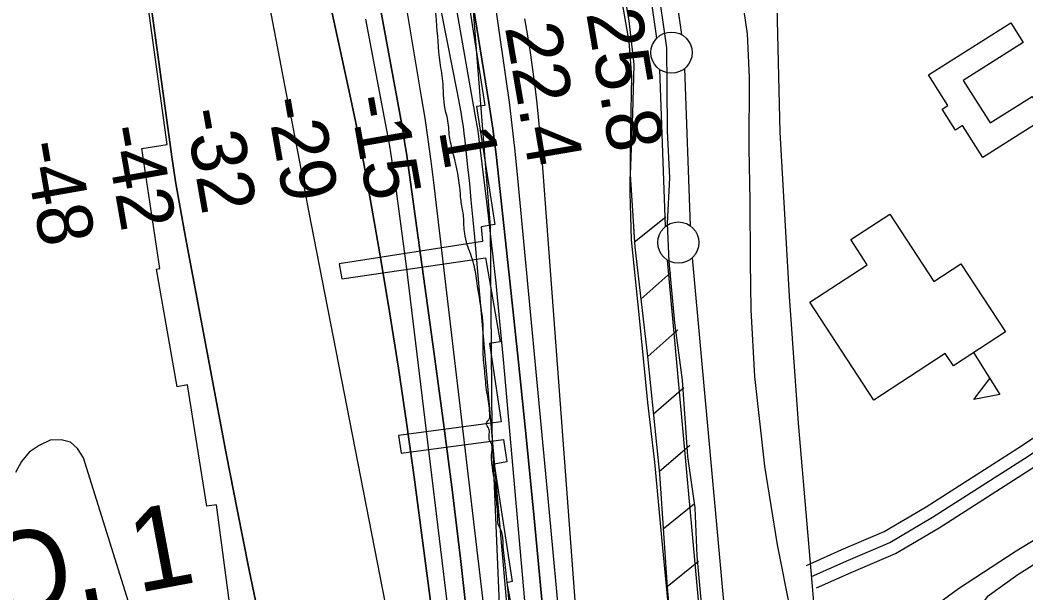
# Model space of a CAD drawing. Extents: x 3419139 to 3457078, y 540382 to 565875.
# Drawn here: x 3439941 to 3441162, y 549163 to 549858 of the extents above; entities that cross this region are included whole.
import ezdxf

# ---------------------------------------------------------------- set-up
doc = ezdxf.new("R2010")
doc.units = 0
for name, color, linetype in [('V-BLDG-OTLN', 7, 'Continuous'), ('V-CHAN-NAID', 7, 'Continuous'), ('V-FLOD-BASE', 7, 'Continuous'), ('V-LEVE-TOET', 7, 'Continuous'), ('V-RIVR-EDGE', 7, 'Continuous'), ('V-RIVR-RANG', 7, 'Continuous'), ('V-ROAD-CNTR', 7, 'Continuous'), ('V-RRAP-FSHR', 7, 'Continuous'), ('V-RRAP-RVMT', 7, 'Continuous'), ('V-SITE-VEGE', 7, 'Continuous'), ('V-SURV-LINE', 7, 'Continuous'), ('V-TOPO-DPTH', 7, 'Continuous'), ('V-TOPO-MAJR', 7, 'Continuous'), ('V-TOPO-MINR', 7, 'Continuous'), ('V-TOPO-WATR', 7, 'Continuous')]:
    doc.layers.add(name, color=color, linetype=linetype)

msp = doc.modelspace()

# ---------------------------------------------------------------- linework, layer by layer
at = {"layer": 'V-BLDG-OTLN'}
msp.add_line((3441098.3, 549454.1), (3441130.3, 549403.3), dxfattribs=at)
for points in [[(3441185.7, 549738.9), (3441109.7, 549690.7), (3441085.1, 549729.7), (3441076.4, 549724.2), (3441060.2, 549749.6), (3441067.2, 549754), (3441043.7, 549791.1), (3441143.4, 549854.3), (3441158.5, 549830.4), (3441085.9, 549784.3), (3441118.6, 549732.7), (3441169.3, 549764.9)], [(3440977.4, 549396.5), (3440899.6, 549515.2), (3440969.3, 549560.8), (3440949.4, 549591.2), (3440996.6, 549622), (3441050.1, 549540.4), (3441083, 549562), (3441137.1, 549479.5), (3441073.9, 549438), (3441063.9, 549453.2)], [(3441130.3, 549403.3), (3441098.8, 549397.1), (3441118, 549422.9)]]:
    msp.add_lwpolyline(points, close=True, dxfattribs=at)
at = {"layer": 'V-FLOD-BASE'}
msp.add_lwpolyline([(3440714, 549906), (3440725.6, 549823.7), (3440726.1, 549777.7), (3440726.5, 549723), (3440729.2, 549666.2), (3440726.5, 549611.2), (3440728.4, 549564.6), (3440735.5, 549490.2), (3440744.9, 549420.6), (3440751.1, 549327.9), (3440760, 549265.6), (3440762.4, 549207.5), (3440767.6, 549149.9), (3440775.3, 549076.3), (3440784.3, 548990.4), (3440791.4, 548896.6), (3440799.1, 548820.8), (3440806.5, 548751.4), (3440810.9, 548694.7), (3440820.2, 548621.4), (3440826.8, 548551.8), (3440832.8, 548485.5), (3440841.1, 548407.2)], dxfattribs=at)
at = {"layer": 'V-LEVE-TOET'}
for points in [[(3440789.6, 548428.9), (3440784.4, 548485.5), (3440775.6, 548556.9), (3440769.9, 548621.4), (3440766.4, 548676.6), (3440760.7, 548752.2), (3440753, 548819.5), (3440745.9, 548897.4), (3440740.2, 548970.5), (3440733.1, 549061.3), (3440727.7, 549150.1), (3440720, 549229.7), (3440711.6, 549321.3), (3440703.1, 549393.6), (3440692.7, 549500.3), (3440683.3, 549590.8), (3440681.5, 549648.3), (3440682.5, 549727.3), (3440683.8, 549788.6), (3440680.5, 549831.5), (3440669.5, 549894.3)], [(3440819.4, 549868.4), (3440823.5, 549841), (3440825.9, 549787.7), (3440825.5, 549702), (3440827, 549638.4), (3440827.1, 549564.5), (3440828.1, 549505.9), (3440832.4, 549425), (3440844.7, 549316.5), (3440859.9, 549220.9), (3440875.7, 549141.6), (3440885.5, 549042.4), (3440892.6, 548950.3), (3440904.7, 548845.2), (3440911.9, 548790.8), (3440921.3, 548737.6), (3440930.4, 548685.2), (3440939.2, 548620.7), (3440947.4, 548543.1), (3440959.2, 548434.1)]]:
    msp.add_lwpolyline(points, dxfattribs=at)
at = {"layer": 'V-RIVR-EDGE'}
msp.add_spline([(3440606.5, 548542), (3440606.2, 548567.3), (3440602.8, 548588.8), (3440599.6, 548602.9), (3440598.6, 548615.3), (3440596.9, 548630.4), (3440593.4, 548648.4), (3440585, 548681.9), (3440580.8, 548696.7), (3440577.3, 548705.2), (3440573.8, 548711.9), (3440574.2, 548719.3), (3440574.9, 548725.6), (3440572.5, 548739), (3440569.7, 548758.4), (3440569.8, 548774.6), (3440568.4, 548805.6), (3440568.5, 548828.2), (3440566.4, 548832.8), (3440561.1, 548843), (3440560.8, 548848.3), (3440560.8, 548854.6), (3440560.5, 548859.6), (3440561.9, 548864.1), (3440565.4, 548871.5), (3440566.5, 548880.3), (3440566.2, 548891.3), (3440563.4, 548894.8), (3440561.3, 548896.9), (3440560.6, 548898.3), (3440558.8, 548902.2), (3440558.5, 548910.7), (3440559.2, 548920.9), (3440561.7, 548937.1), (3440562.4, 548945.5), (3440562.4, 548952.6), (3440561.8, 548959.3), (3440559.7, 548969.1), (3440557.6, 548979), (3440555.5, 548989.9), (3440553, 548999.8), (3440549.9, 549013.6), (3440549.9, 549021.7), (3440550, 549031.9), (3440548.9, 549037.9), (3440547.2, 549043.2), (3440545.1, 549050.9), (3440542.7, 549081.6), (3440541.7, 549102.7), (3440541.4, 549115.8), (3440539.6, 549121.4), (3440538.2, 549126.4), (3440533.7, 549164.8), (3440530.3, 549193.7), (3440527.5, 549221.9), (3440525.8, 549236), (3440521.2, 549247.6), (3440520.9, 549255.4), (3440519.2, 549278.3), (3440518.5, 549290.3), (3440515.4, 549308.2), (3440514.4, 549315.3), (3440513.7, 549332.9), (3440512.7, 549345.6), (3440510.6, 549348.8), (3440510.6, 549351.9), (3440510.6, 549355.5), (3440510.9, 549359), (3440510.2, 549361.5), (3440507.1, 549368.5), (3440511, 549374.1), (3440511.3, 549378.4), (3440511, 549384), (3440507.9, 549405.9), (3440505.1, 549431.6), (3440503.1, 549458.4), (3440503.2, 549487.3), (3440501.4, 549504.5), (3440495.9, 549538.4), (3440492.1, 549561), (3440488.2, 549573.3), (3440484, 549584.9), (3440480.9, 549598.7), (3440479.9, 549608.6), (3440479.5, 549619.1), (3440476.7, 549636.4), (3440475, 549654.4), (3440466, 549699.9), (3440462.2, 549718.9), (3440459.4, 549740.7), (3440458, 549745.3), (3440454.6, 549780.2), (3440451.1, 549806), (3440446.6, 549857.1), (3440441.5, 549900.4), (3440437, 549938.1), (3440435.9, 549948.7), (3440428.7, 549999.8), (3440424.8, 550021.7), (3440423.5, 550042.1), (3440422.2, 550073.5), (3440419.1, 550101), (3440415.2, 550128.5), (3440409, 550157.7), (3440408, 550174.3), (3440409.4, 550193.7), (3440408.7, 550210.2), (3440405.6, 550227.2), (3440403.9, 550234.9), (3440395.8, 550244.4), (3440387, 550251.5), (3440378.6, 550256.1), (3440372.9, 550264.2), (3440367, 550279), (3440361.8, 550306.2), (3440354.8, 550346), (3440348.9, 550377.8), (3440347.9, 550389.7), (3440349, 550403.1), (3440352.5, 550418.3), (3440352.5, 550423.6), (3440351.1, 550427.4), (3440341.7, 550443), (3440332.5, 550450), (3440330.1, 550453.6), (3440325.2, 550467), (3440324.2, 550488.8), (3440325.3, 550503.3), (3440325.7, 550521.2), (3440325, 550535.3), (3440320.4, 550554.4), (3440313.8, 550578.3), (3440311.7, 550592.1), (3440311.8, 550613.2), (3440308, 550646.7), (3440307.7, 550672.1), (3440307.7, 550684.4), (3440304.2, 550695.4), (3440300.4, 550703.8), (3440296.5, 550714.4), (3440295.5, 550723.9), (3440295.9, 550738.4), (3440295.9, 550747.5), (3440291.4, 550757.4), (3440287.5, 550775.4), (3440284.4, 550791.6), (3440282.7, 550806.4), (3440279.9, 550812.8), (3440279.9, 550816.6), (3440276.7, 550830.7), (3440272.2, 550850.1), (3440262.8, 550882.2), (3440257.2, 550910.8), (3440255.5, 550936.2), (3440255.5, 550947.8), (3440257.7, 550957.3), (3440260.5, 550966.1), (3440264.4, 550979.8), (3440264.1, 550991.1), (3440262, 551009.8), (3440258.5, 551023.5), (3440256.4, 551033.4), (3440256.5, 551038.7), (3440260.7, 551046.4), (3440260.7, 551055.2), (3440257.2, 551067.9), (3440250.9, 551083.8), (3440245.7, 551098.3), (3440234.1, 551119.4), (3440230.2, 551127.6), (3440228.1, 551132.5), (3440221.5, 551140.3), (3440218.3, 551147), (3440212.4, 551159.7), (3440202.6, 551196.3), (3440198, 551213.3), (3440198.1, 551219.3), (3440197.4, 551227.4), (3440196.7, 551237.6), (3440192.8, 551245.7), (3440189.7, 551257), (3440187.3, 551269), (3440183.1, 551289.4), (3440182.4, 551301.7), (3440179.6, 551313.7), (3440175.4, 551332.4), (3440174.1, 551344.8), (3440172.7, 551357.1), (3440172.3, 551367.7), (3440172, 551383.2), (3440172.4, 551398.3), (3440171.1, 551413.5), (3440170, 551424.1), (3440167.9, 551425.8), (3440162.6, 551434.3), (3440159.9, 551454.4), (3440156, 551470.6), (3440152.9, 551490.3), (3440152.9, 551495.3), (3440155.8, 551496.3), (3440155.4, 551498.8), (3440149.8, 551521.4), (3440146.3, 551534.8), (3440142.2, 551559.1)], degree=3, dxfattribs=at)
at = {"layer": 'V-ROAD-CNTR'}
for points in [[(3440806.5, 550262.5), (3440829.5, 550127), (3440847.5, 549995.6), (3440859.7, 549874.2), (3440863.2, 549721.4), (3440874.4, 549522.6), (3440885.6, 549368.5), (3440909.1, 549095.1), (3440935, 548822.8), (3440956.6, 548577.1), (3440983.9, 548304.6)], [(3440895.5, 549196), (3440937.8, 549215), (3440990, 549237.1), (3441040.8, 549267.2), (3441152, 549338.2), (3441296.5, 549433.6), (3441402.1, 549505.5)], [(3440901.6, 549182.3), (3440943.8, 549201.2), (3440996.8, 549223.7), (3441048.7, 549254.5), (3441160.1, 549325.6), (3441304.9, 549421.2), (3441410.6, 549493.1)], [(3440907.7, 549168.6), (3440949.8, 549187.5), (3441003.6, 549210.3), (3441056.5, 549241.7), (3441168.3, 549313), (3441313.2, 549408.7), (3441419, 549480.7)]]:
    msp.add_lwpolyline(points, dxfattribs=at)
at = {"layer": 'V-RRAP-FSHR'}
for p, q in [((3440686.8, 549588.4), (3440724.9, 549618.8)), ((3440694.6, 549518.9), (3440731.1, 549551.4)), ((3440702.9, 549449.3), (3440739.3, 549481.9)), ((3440709.9, 549379.7), (3440746.9, 549411.6)), ((3440716.9, 549310), (3440753.9, 549341.9)), ((3440721.7, 549240.2), (3440759.7, 549270.9)), ((3440726.5, 549170.4), (3440764.5, 549201))]:
    msp.add_line(p, q, dxfattribs=at)
for points in [[(3439977.8, 552420.6), (3440106.4, 551780.9), (3440172.3, 551404.3), (3440232, 551110), (3440392.8, 550607.1), (3440489.2, 549894.4), (3440511.6, 549607.3), (3440513.8, 549359.3), (3440532, 548929.5), (3440619.8, 548305.6), (3440691.1, 548058.6), (3440757.3, 547660.9), (3440767.5, 547537.4), (3440783.9, 547406), (3441072.2, 545849.7)], [(3440614, 550282.7), (3440634.7, 550166.5), (3440663.2, 549954.4), (3440680, 549856.7), (3440686, 549803.7), (3440684.6, 549744.2), (3440681.7, 549670.3), (3440687.2, 549581.9), (3440702.8, 549449.4), (3440717.2, 549307.2), (3440726.6, 549169.2), (3440746, 548958.9), (3440764.7, 548717.6), (3440769.3, 548594), (3440791.4, 548435.6)], [(3440685.6, 549606.4), (3440687.2, 549581.9), (3440702.8, 549449.4), (3440717.2, 549307.2), (3440726.6, 549169.2), (3440729.1, 549142.2)]]:
    msp.add_lwpolyline(points, dxfattribs=at)
at = {"layer": 'V-RRAP-RVMT'}
for points in [[(3440106.8, 549555.5), (3440110.8, 549556.1), (3440089, 549701.8), (3440119.9, 549706.7), (3440046.8, 550237.4), (3440021.9, 550234.5), (3439978.8, 550522.5), (3439962.8, 550519.8), (3439939.3, 550673.8), (3439942.1, 550674.4), (3439921.8, 550804.9), (3439910.5, 550803.2), (3439869, 551057.2), (3439876.9, 551058.9), (3439860.3, 551163), (3439850.8, 551161.3), (3439834.7, 551249.1)], [(3440484.7, 549885.6), (3440505.2, 549754.1), (3440495.1, 549752.7), (3440517.6, 549609.5), (3440500.7, 549606.9), (3440502.5, 549589.1), (3440328.6, 549562), (3440331.8, 549543.5), (3440506, 549569.2), (3440523.7, 549467.1)], [(3440292.6, 548413.6), (3440272.2, 548548.6), (3440262.2, 548546.9), (3440219.9, 548847.1), (3440226.4, 548848.2), (3440205.9, 548992.5), (3440209.7, 548993.1), (3440190.6, 549137.2), (3440197, 549138.4), (3440179.7, 549269.5), (3440168, 549267.7), (3440144.6, 549415), (3440132.1, 549412.7), (3440106.8, 549555.5)], [(3440523.7, 549467.1), (3440510.8, 549465), (3440524.9, 549370.1), (3440400.6, 549353.5), (3440403.9, 549332.3), (3440527.9, 549348.7), (3440531.9, 549321.7), (3440516.8, 549318.9), (3440538.5, 549176.6), (3440531.9, 549174.9), (3440536.6, 549150.8)]]:
    msp.add_lwpolyline(points, dxfattribs=at)
at = {"layer": 'V-SITE-VEGE'}
msp.add_lwpolyline([(3441195.7, 549212.1), (3441151.9, 549184.5), (3441115, 549157.7), (3441108.1, 549148.4), (3441103.8, 549140.2), (3441093.6, 549134.8), (3441087.5, 549135.5), (3441074, 549135.5), (3441054.9, 549124.1), (3441030.7, 549107.5), (3441015, 549100), (3441007.5, 549100), (3441002.4, 549104.3), (3441001.8, 549110.6), (3441026.9, 549129), (3441080.1, 549168.1), (3441150.2, 549213.8), (3441251.7, 549275.4)], dxfattribs=at)
at = {"layer": 'V-SURV-LINE'}
for points in [[(3440714.1, 549835.8), (3440635.6, 550387)], [(3440665.3, 550391.2), (3440743.8, 549840)], [(3440724.4, 549607), (3440717.5, 549797.6)], [(3440747.5, 549798.7), (3440754.4, 549608.1)], [(3440823.7, 548506.7), (3440727, 549566.3)], [(3440756.9, 549569.1), (3440853.6, 548509.4)]]:
    msp.add_lwpolyline(points, dxfattribs=at)
for centre in [(3440731.8, 549818.1), (3440740.1, 549587.6)]:
    msp.add_circle(centre, 25, dxfattribs=at)
at = {"layer": 'V-TOPO-DPTH'}
for points in [[(3440541.8, 549039.1), (3440492.6, 549598.6), (3440490.7, 549618.9), (3440488.8, 549639.1), (3440486.9, 549659.4), (3440484.8, 549679.6), (3440482.4, 549702.8), (3440481.4, 549711.4), (3440480.4, 549720), (3440479.2, 549728.6), (3440477.9, 549737.2), (3440476.4, 549745.7), (3440475, 549754.3), (3440473.4, 549762.8), (3440471.8, 549771.3), (3440286.6, 550709.8)], [(3440541.8, 549039.1), (3440492.6, 549598.6), (3440490.7, 549618.9), (3440488.8, 549639.1), (3440486.9, 549659.4), (3440484.8, 549679.6), (3440482.4, 549702.8), (3440481.4, 549711.4), (3440480.4, 549720), (3440479.2, 549728.6), (3440477.9, 549737.2), (3440476.4, 549745.7), (3440475, 549754.3), (3440473.4, 549762.8), (3440471.8, 549771.3), (3440286.6, 550709.8)], [(3440408, 549029.7), (3440295, 549609.5), (3440292.6, 549622.2), (3440290.2, 549634.8), (3440287.8, 549647.5), (3440285.4, 549660.1), (3440283.1, 549672.8), (3440280.7, 549685.5), (3440278.3, 549698.1), (3440275.9, 549710.8), (3440271.7, 549732.1), (3440267.2, 549755.5), (3440262.6, 549778.8), (3440258.1, 549802.2), (3440253.6, 549825.5), (3440087.1, 550694.6)], [(3440408, 549029.7), (3440295, 549609.5), (3440292.6, 549622.2), (3440290.2, 549634.8), (3440287.8, 549647.5), (3440285.4, 549660.1), (3440283.1, 549672.8), (3440280.7, 549685.5), (3440278.3, 549698.1), (3440275.9, 549710.8), (3440271.7, 549732.1), (3440267.2, 549755.5), (3440262.6, 549778.8), (3440258.1, 549802.2), (3440253.6, 549825.5), (3440087.1, 550694.6)], [(3440228.5, 550685.2), (3440404.4, 549730.8), (3440406.5, 549719.2), (3440408.4, 549707.6), (3440410.2, 549695.9), (3440411.9, 549684.2), (3440443.5, 549455.3), (3440454.7, 549371.8), (3440465.5, 549288.2), (3440475.6, 549204.5), (3440485.2, 549120.8), (3440495.9, 549025.3), (3440499.9, 548989.3), (3440503.9, 548953.3), (3440507.8, 548917.3), (3440511.7, 548881.3), (3440569.5, 548341.4)], [(3440228.5, 550685.2), (3440404.4, 549730.8), (3440406.5, 549719.2), (3440408.4, 549707.6), (3440410.2, 549695.9), (3440411.9, 549684.2), (3440443.5, 549455.3), (3440454.7, 549371.8), (3440465.5, 549288.2), (3440475.6, 549204.5), (3440485.2, 549120.8), (3440495.9, 549025.3), (3440499.9, 548989.3), (3440503.9, 548953.3), (3440507.8, 548917.3), (3440511.7, 548881.3), (3440569.5, 548341.4)], [(3440433, 550236.4), (3440510.3, 549757.6), (3440512.7, 549741.8), (3440515, 549726), (3440517, 549710.2), (3440518.9, 549694.4), (3440536.1, 549537), (3440546.2, 549442.5), (3440555.9, 549347.9), (3440565.1, 549253.3), (3440573.9, 549158.6), (3440587.7, 549007.5), (3440589.5, 548988.1), (3440591.3, 548968.7), (3440593.3, 548949.3), (3440595.4, 548929.9), (3440640.6, 548511.5), (3440647.7, 548446.5)], [(3440526.8, 548431), (3440516.1, 548516.9), (3440505.7, 548602.8), (3440495.6, 548688.7), (3440485.7, 548774.7), (3440470.2, 548912.6), (3440468.2, 548929.7), (3440466.2, 548946.7), (3440464, 548963.7), (3440461.9, 548980.7), (3440419.4, 549303.2), (3440410.3, 549369.3), (3440400.6, 549435.3), (3440390.2, 549501.2), (3440379.1, 549567), (3440368.3, 549629.2), (3440362.1, 549663.8), (3440355.5, 549698.4), (3440348.6, 549732.9), (3440341.4, 549767.3), (3440256.6, 550158.7)], [(3440256.6, 550158.7), (3440341.4, 549767.3), (3440348.6, 549732.9), (3440355.5, 549698.4), (3440362.1, 549663.8), (3440368.3, 549629.2), (3440379.1, 549567), (3440390.2, 549501.2), (3440400.6, 549435.3), (3440410.3, 549369.3), (3440419.4, 549303.2), (3440461.9, 548980.7), (3440464, 548963.7), (3440466.2, 548946.7), (3440468.2, 548929.7), (3440470.2, 548912.6), (3440485.7, 548774.7), (3440495.6, 548688.7), (3440505.7, 548602.8), (3440516.1, 548516.9), (3440526.8, 548431)], [(3440097.3, 549898.4), (3440121.7, 549718.3), (3440125.9, 549688.9), (3440130.4, 549659.4), (3440135.4, 549630.1), (3440140.7, 549600.8), (3440191.5, 549331.8), (3440205, 549261.9), (3440219, 549192.1), (3440233.6, 549122.4), (3440248.6, 549052.8), (3440269.7, 548957.1), (3440274.5, 548935.4), (3440279.2, 548913.8), (3440283.8, 548892.1), (3440288.4, 548870.4), (3440342.3, 548614.6), (3440360.9, 548526.1), (3440379.4, 548437.5)], [(3440379.4, 548437.5), (3440360.9, 548526.1), (3440342.3, 548614.6), (3440288.4, 548870.4), (3440283.8, 548892.1), (3440279.2, 548913.8), (3440274.5, 548935.4), (3440269.7, 548957.1), (3440248.6, 549052.8), (3440233.6, 549122.4), (3440219, 549192.1), (3440205, 549261.9), (3440191.5, 549331.8), (3440140.7, 549600.8), (3440135.4, 549630.1), (3440130.4, 549659.4), (3440125.9, 549688.9), (3440121.7, 549718.3), (3440097.3, 549898.4)]]:
    msp.add_lwpolyline(points, dxfattribs=at)
at = {"layer": 'V-TOPO-MAJR'}
msp.add_lwpolyline([(3440141.2, 548889.5), (3440140.5, 548893.6), (3440138.2, 548905), (3440136.6, 548912.8), (3440135, 548920.5), (3440133.3, 548928.3), (3440131.6, 548936), (3440121.2, 548981.2), (3440113.9, 549011.4), (3440106.1, 549041.5), (3440097.6, 549071.5), (3440088.6, 549101.2), (3440018.1, 549326.6), (3440011.1, 549337.7), (3440002.4, 549345.5), (3439991.1, 549348.3), (3439978, 549347.8), (3439964.3, 549341.5), (3439952.3, 549333.2), (3439943.1, 549322), (3439935.6, 549308.8)], dxfattribs=at)
at = {"layer": 'V-TOPO-MINR'}
for points in [[(3440629.3, 548413.3), (3440619.1, 548505.2), (3440609, 548597.1), (3440599.2, 548689.1), (3440589.5, 548781), (3440576.7, 548905.5), (3440573.7, 548935.3), (3440570.8, 548965.1), (3440568, 548994.8), (3440565.3, 549024.6), (3440527.8, 549445.6), (3440523.5, 549491.9), (3440518.9, 549538.2), (3440513.8, 549584.4), (3440508.4, 549630.6), (3440498.8, 549709.6), (3440497.9, 549716.3), (3440497, 549722.9), (3440496, 549729.5), (3440494.9, 549736.1), (3440320.8, 550728.6)], [(3440408, 549029.7), (3440295, 549609.5), (3440292.6, 549622.2), (3440290.2, 549634.8), (3440287.8, 549647.5), (3440285.4, 549660.1), (3440283.1, 549672.8), (3440280.7, 549685.5), (3440278.3, 549698.1), (3440275.9, 549710.8), (3440271.7, 549732.1), (3440267.2, 549755.5), (3440262.6, 549778.8), (3440258.1, 549802.2), (3440253.6, 549825.5), (3440087.1, 550694.6)], [(3440569.5, 548341.4), (3440511.7, 548881.3), (3440507.8, 548917.3), (3440503.9, 548953.3), (3440499.9, 548989.3), (3440495.9, 549025.3), (3440485.2, 549120.8), (3440475.6, 549204.5), (3440465.5, 549288.2), (3440454.7, 549371.8), (3440443.5, 549455.3), (3440411.9, 549684.2), (3440410.2, 549695.9), (3440408.4, 549707.6), (3440406.5, 549719.2), (3440404.4, 549730.8), (3440228.5, 550685.2)], [(3440647.7, 548446.5), (3440640.6, 548511.5), (3440595.4, 548929.9), (3440593.3, 548949.3), (3440591.3, 548968.7), (3440589.5, 548988.1), (3440587.7, 549007.5), (3440573.9, 549158.6), (3440565.1, 549253.3), (3440555.9, 549347.9), (3440546.2, 549442.5), (3440536.1, 549537), (3440518.9, 549694.4), (3440517, 549710.2), (3440515, 549726), (3440512.7, 549741.8), (3440510.3, 549757.6), (3440433, 550236.4)], [(3440526.8, 548431), (3440516.1, 548516.9), (3440505.7, 548602.8), (3440495.6, 548688.7), (3440485.7, 548774.7), (3440470.2, 548912.6), (3440468.2, 548929.7), (3440466.2, 548946.7), (3440464, 548963.7), (3440461.9, 548980.7), (3440419.4, 549303.2), (3440410.3, 549369.3), (3440400.6, 549435.3), (3440390.2, 549501.2), (3440379.1, 549567), (3440368.3, 549629.2), (3440362.1, 549663.8), (3440355.5, 549698.4), (3440348.6, 549732.9), (3440341.4, 549767.3), (3440256.6, 550158.7)], [(3440580.5, 548421.9), (3440526, 548951.4), (3440525.7, 548954.3), (3440525.5, 548957.1), (3440525.2, 548959.9), (3440524.9, 548962.8), (3440522.3, 548988.1), (3440520.7, 549003.6), (3440519, 549019.1), (3440517.3, 549034.6), (3440515.5, 549050), (3440443.3, 549660.4), (3440440.1, 549686.4), (3440436.6, 549712.5), (3440432.7, 549738.4), (3440428.6, 549764.3), (3440394.9, 549966.3)], [(3440700.7, 548174.4), (3440612.6, 548952.8), (3440611.6, 548962.4), (3440610.5, 548972.1), (3440609.6, 548981.7), (3440608.7, 548991.4), (3440601.6, 549068.1), (3440597.1, 549116.1), (3440592.6, 549164.1), (3440588.2, 549212.1), (3440583.6, 549260.1), (3440544.6, 549674.3), (3440541.7, 549702.2), (3440538.6, 549730.1), (3440535.1, 549758), (3440531.3, 549785.8), (3440511.7, 549921.2)], [(3440097.3, 549898.4), (3440121.7, 549718.3), (3440125.9, 549688.9), (3440130.4, 549659.4), (3440135.4, 549630.1), (3440140.7, 549600.8), (3440191.5, 549331.8), (3440205, 549261.9), (3440219, 549192.1), (3440233.6, 549122.4), (3440248.6, 549052.8), (3440269.7, 548957.1), (3440274.5, 548935.4), (3440279.2, 548913.8), (3440283.8, 548892.1), (3440288.4, 548870.4), (3440342.3, 548614.6), (3440360.9, 548526.1), (3440379.4, 548437.5)], [(3440542.4, 548431.6), (3440532.9, 548513.3), (3440523.6, 548595.1), (3440490, 548897.7), (3440487.1, 548923.8), (3440484.1, 548949.8), (3440481, 548975.9), (3440477.9, 549001.9), (3440410.1, 549559), (3440407.1, 549583.3), (3440403.9, 549607.5), (3440400.6, 549631.8), (3440397.2, 549656), (3440390.8, 549699.7), (3440390.5, 549702), (3440389.7, 549706.8), (3440389.3, 549709.1), (3440370.7, 549807.3), (3440360.9, 549858.7)], [(3440750.7, 548183.4), (3440635.6, 548922.1), (3440634.3, 548931), (3440633, 548939.8), (3440631.8, 548948.6), (3440630.7, 548957.5), (3440628.6, 548974.1), (3440628.5, 548975.2), (3440628.4, 548976.3), (3440628, 548980.6), (3440627.7, 548983.3), (3440627.5, 548985.9), (3440627.3, 548988.6), (3440627.1, 548991.3), (3440574.5, 549694.4), (3440572.8, 549715.1), (3440570.9, 549735.7), (3440568.8, 549756.4), (3440566.4, 549777), (3440563.7, 549797.6), (3440560.8, 549818.1), (3440557.5, 549838.6), (3440554, 549859.1)]]:
    msp.add_lwpolyline(points, dxfattribs=at)
at = {"layer": 'V-TOPO-WATR'}
msp.add_lwpolyline([(3440541.8, 549039.1), (3440492.6, 549598.6), (3440490.7, 549618.9), (3440488.8, 549639.1), (3440486.9, 549659.4), (3440484.8, 549679.6), (3440482.4, 549702.8), (3440481.4, 549711.4), (3440480.4, 549720), (3440479.2, 549728.6), (3440477.9, 549737.2), (3440476.4, 549745.7), (3440475, 549754.3), (3440473.4, 549762.8), (3440471.8, 549771.3), (3440286.6, 550709.8)], dxfattribs=at)

# ---------------------------------------------------------------- texts
at = {"layer": 'V-CHAN-NAID'}
for p in [(3438186.9, 549595.1), (3438331.2, 548834.5)]:
    msp.add_text('SUGARLAND EQULION NO. 1 ', height=100, rotation=10.5984, dxfattribs=at).set_placement(p)
at = {"layer": 'V-RIVR-RANG'}
for s, rotation, p in [('25.8', 279.6783, (3440628.1, 549866.1)), ('22.4', 279.6783, (3440529.5, 549849.1)), ('-29', 279.9599, (3440239.9, 549760.8)), ('-15', 279.9599, (3440341, 549763)), ('-32', 279.9599, (3440140.7, 549747.1)), ('-42', 279.9599, (3440042.8, 549726.4)), ('1', 279.6783, (3440449.4, 549723.8)), ('-48', 279.9599, (3439944.7, 549707.3))]:
    msp.add_text(s, height=67, rotation=rotation, dxfattribs=at).set_placement(p)

doc.saveas('drawing.dxf')
